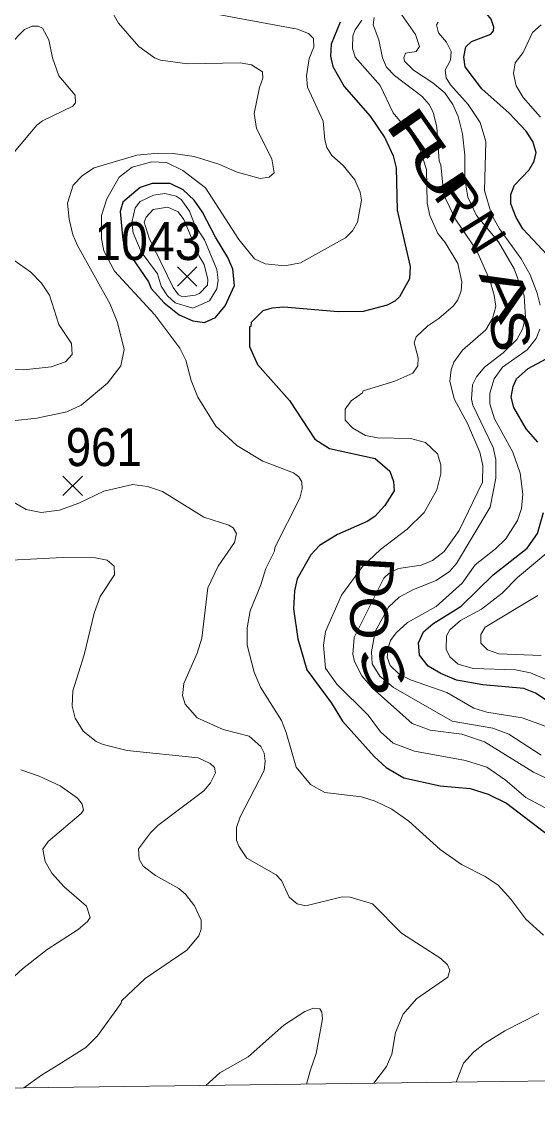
# Model space of a CAD drawing. Extents: x 265 to 291.4, y 7731.5 to 7759.6.
# Drawn here: x 270.921 to 272.01, y 7731.544 to 7733.87 of the extents above; entities that cross this region are included whole.
import ezdxf
from ezdxf.enums import TextEntityAlignment as Align

# ---------------------------------------------------------------- set-up
doc = ezdxf.new("R2010")
doc.units = 0
doc.header["$LTSCALE"] = 0.032
for name, color, linetype, lineweight in [('1', 7, 'Continuous', 25), ('2', 7, 'Continuous', 13), ('21', 7, 'Continuous', 25), ('61', 7, 'Continuous', 13), ('63', 7, 'Continuous', 25)]:
    doc.layers.add(name, color=color, linetype=linetype, lineweight=lineweight)

msp = doc.modelspace()

# ---------------------------------------------------------------- linework, layer by layer
at = {"layer": '1'}
for points in [[(271.9111, 7733.8446), (271.9166, 7733.8518), (271.9174, 7733.8589), (271.9118, 7733.8764), (271.8657, 7733.9329), (271.8538, 7733.9552), (271.8466, 7733.9775)], [(271.5929, 7733.8701), (271.5738, 7733.8231), (271.5722, 7733.7977), (271.5777, 7733.7762), (271.6016, 7733.734), (271.6565, 7733.6712), (271.6875, 7733.6259), (271.705, 7733.5877), (271.7114, 7733.5622), (271.713, 7733.4731), (271.7408, 7733.3538), (271.7392, 7733.3283), (271.7185, 7733.2902), (271.7082, 7733.2806), (271.6923, 7733.2726), (271.6414, 7733.2591), (271.5889, 7733.2583), (271.4743, 7733.2679), (271.4489, 7733.2663), (271.4298, 7733.2607), (271.4051, 7733.2361), (271.4043, 7733.2273), (271.4019, 7733.2265), (271.4019, 7733.1852), (271.4186, 7733.147), (271.4863, 7733.0714), (271.5396, 7732.9895), (271.5706, 7732.9696), (271.6669, 7732.9489), (271.6979, 7732.9218), (271.7058, 7732.9004), (271.7066, 7732.8805), (271.6875, 7732.8495), (271.666, 7732.8264), (271.6501, 7732.816), (271.5873, 7732.7882), (271.5491, 7732.7651), (271.5308, 7732.7452), (271.5022, 7732.6951), (271.4966, 7732.6697), (271.4942, 7732.6315), (271.5038, 7732.5679), (271.5228, 7732.5026), (271.5746, 7732.4326), (271.5976, 7732.3945)], [(272.0717, 7733.3347), (271.9787, 7733.4334), (271.9643, 7733.4572), (271.9532, 7733.4866), (271.9532, 7733.5057), (271.9612, 7733.5256), (271.9922, 7733.5582), (272.0025, 7733.5765), (272.0065, 7733.5948), (271.9993, 7733.6179), (271.9858, 7733.6394), (271.95, 7733.6776), (271.892, 7733.7293), (271.857, 7733.7754), (271.8538, 7733.7961), (271.8585, 7733.8176), (271.8705, 7733.8287), (271.9111, 7733.8446)], [(272.0105, 7732.9831), (271.9858, 7733.0117), (271.9596, 7733.0563), (271.954, 7733.0786), (271.958, 7733.1008), (271.9651, 7733.1167), (271.9898, 7733.139), (272.028, 7733.1589)], [(272.0487, 7732.4247), (272.0049, 7732.4533), (271.9803, 7732.4636), (271.8944, 7732.4708), (271.8387, 7732.4811), (271.8053, 7732.4947), (271.779, 7732.5106), (271.7607, 7732.5337), (271.7583, 7732.5599), (271.7686, 7732.583), (271.7885, 7732.5997), (271.8482, 7732.637), (271.9158, 7732.7031), (271.9874, 7732.7596), (272.0097, 7732.7906), (272.0224, 7732.8351)], [(271.5976, 7732.3945), (271.6644, 7732.3197), (271.6899, 7732.2966), (271.7273, 7732.2751), (271.8037, 7732.2576), (271.8673, 7732.252), (271.9055, 7732.2401)], [(271.9055, 7732.2401), (271.9437, 7732.221), (272.0479, 7732.1415), (272.106, 7732.0866), (272.1601, 7732.0468), (272.1855, 7732.0357), (272.211, 7732.0293), (272.2746, 7732.0245), (272.2953, 7732.0197), (272.304, 7732.0015), (272.3016, 7731.9888), (272.2451, 7731.8487), (272.2268, 7731.8233), (272.1616, 7731.762), (272.1417, 7731.7374), (272.1378, 7731.7247), (272.1339, 7731.7104), (272.1322, 7731.6905), (272.1339, 7731.679), (272.138, 7731.6663), (272.1444, 7731.6493), (272.1533, 7731.6367)]]:
    msp.add_lwpolyline(points, dxfattribs=at)
msp.add_lwpolyline([(271.3665, 7733.3484), (271.3559, 7733.3729), (271.3295, 7733.4159), (271.3025, 7733.4684), (271.285, 7733.4938), (271.2619, 7733.5161), (271.2341, 7733.5296), (271.1959, 7733.5296), (271.1705, 7733.5208), (271.1339, 7733.4898), (271.1283, 7733.4699), (271.1339, 7733.4103), (271.1442, 7733.3864), (271.1887, 7733.322), (271.1943, 7733.3077), (271.2214, 7733.2774), (271.2532, 7733.252), (271.2818, 7733.2392), (271.3065, 7733.236), (271.3296, 7733.2464), (271.3502, 7733.2711), (271.3701, 7733.314)], close=True, dxfattribs=at)
at = {"layer": '2'}
for points in [[(270.9096, 7734.0976), (270.9541, 7734.1175), (270.9668, 7734.1167), (270.9796, 7734.1111), (271.0082, 7734.0761), (271.0416, 7734.026), (271.0917, 7733.9266), (271.1251, 7733.8677), (271.1681, 7733.8184), (271.2007, 7733.7945), (271.2134, 7733.7897), (271.2707, 7733.7818), (271.3821, 7733.7842), (271.4059, 7733.7794), (271.429, 7733.7651), (271.4298, 7733.7515), (271.4226, 7733.7317), (271.4115, 7733.6768), (271.4163, 7733.645), (271.4489, 7733.5813)], [(272.0169, 7732.3228), (271.9492, 7732.3666), (271.915, 7732.3793), (271.8291, 7732.3944), (271.7058, 7732.4652), (271.6764, 7732.4891), (271.6605, 7732.5154), (271.6589, 7732.5408), (271.6668, 7732.5838), (271.6947, 7732.6347), (271.7178, 7732.6562), (271.748, 7732.6721), (271.7957, 7732.6912), (271.8236, 7732.7102), (271.8387, 7732.727), (271.9095, 7732.8463), (271.9214, 7732.9075), (271.9214, 7732.9465), (271.9158, 7732.972), (271.8729, 7733.0611), (271.8705, 7733.0738), (271.8721, 7733.104), (271.8808, 7733.1215), (271.8975, 7733.1414), (271.9373, 7733.1716), (271.9659, 7733.2003), (271.9779, 7733.2218), (271.9842, 7733.2472), (271.9811, 7733.2918), (271.9604, 7733.349), (271.927, 7733.4063), (271.8808, 7733.462), (271.8625, 7733.5002), (271.8562, 7733.5384), (271.8562, 7733.5893), (271.8514, 7733.6338), (271.8419, 7733.6704), (271.8307, 7733.6959), (271.814, 7733.7205), (271.7886, 7733.742), (271.748, 7733.7682), (271.7289, 7733.7873), (271.7273, 7733.7945), (271.7305, 7733.804), (271.7535, 7733.808), (271.7607, 7733.8184), (271.752, 7733.8438), (271.7026, 7733.9138)], [(272.0224, 7731.9426), (271.985, 7731.9768), (271.9532, 7732.019), (271.9262, 7732.0484), (271.8991, 7732.0667), (271.849, 7732.0922), (271.8037, 7732.1232), (271.7376, 7732.1836), (271.7019, 7732.2083), (271.6669, 7732.2258), (271.6382, 7732.2346), (271.5603, 7732.2441), (271.53, 7732.2608), (271.4998, 7732.2974), (271.4791, 7732.3706), (271.4688, 7732.396), (271.425, 7732.466), (271.4115, 7732.4979), (271.3964, 7732.5551), (271.3964, 7732.5917), (271.4027, 7732.6275), (271.4258, 7732.6824), (271.4362, 7732.7166), (271.4545, 7732.7532), (271.4552, 7732.7612), (271.5077, 7732.8654), (271.5125, 7732.8845), (271.5117, 7732.8996), (271.5054, 7732.9099), (271.4942, 7732.9187), (271.4298, 7732.9433), (271.3749, 7732.9759), (271.3304, 7733.0173), (271.2922, 7733.0786), (271.2786, 7733.1136), (271.2675, 7733.1565), (271.2548, 7733.182), (271.2015, 7733.252), (271.1168, 7733.3439), (271.0939, 7733.3871), (271.0893, 7733.4127), (271.0893, 7733.462), (271.1005, 7733.497), (271.1267, 7733.5423), (271.1538, 7733.5638), (271.1951, 7733.5749), (271.2262, 7733.5733), (271.2612, 7733.5566), (271.3089, 7733.52), (271.3789, 7733.4111), (271.4123, 7733.3705), (271.4346, 7733.3594), (271.4759, 7733.3554), (271.5093, 7733.3618), (271.604, 7733.4143), (271.6191, 7733.4294), (271.6295, 7733.4477), (271.6382, 7733.4938), (271.635, 7733.5113), (271.6239, 7733.5368), (271.5992, 7733.567), (271.5754, 7733.5885), (271.565, 7733.6052), (271.5603, 7733.6211), (271.5571, 7733.6609), (271.5237, 7733.7325), (271.5221, 7733.7563), (271.5276, 7733.7929), (271.5372, 7733.8168), (271.5364, 7733.8351), (271.526, 7733.8462), (271.503, 7733.855), (271.3089, 7733.8907)], [(271.639, 7733.8741), (271.6247, 7733.8534), (271.6199, 7733.8406), (271.6191, 7733.8152), (271.6247, 7733.7961), (271.6772, 7733.7364), (271.705, 7733.6784), (271.7416, 7733.6338), (271.7615, 7733.6004), (271.775, 7733.559), (271.7766, 7733.4874), (271.7822, 7733.462), (271.7989, 7733.4238), (271.8148, 7733.4047), (271.8411, 7733.3602), (271.8498, 7733.322), (271.8482, 7733.3029), (271.8411, 7733.2838), (271.8323, 7733.2711), (271.8013, 7733.244), (271.7782, 7733.2289), (271.7535, 7733.2058), (271.7488, 7733.1931), (271.7575, 7733.1613), (271.7567, 7733.1446), (271.7464, 7733.1287), (271.7082, 7733.112), (271.6414, 7733.0913)], [(271.6645, 7733.8796), (271.6629, 7733.8645), (271.6748, 7733.8327), (271.682, 7733.7945), (271.6907, 7733.7746), (271.7074, 7733.7571), (271.7663, 7733.7126), (271.7806, 7733.6959), (271.7893, 7733.68), (271.7973, 7733.6481), (271.8021, 7733.5765), (271.8053, 7733.5686), (271.8116, 7733.5049), (271.8371, 7733.4524), (271.8808, 7733.3888), (271.9087, 7733.3252), (271.9182, 7733.2933), (271.9214, 7733.2695), (271.9142, 7733.244), (271.9007, 7733.2202), (271.8514, 7733.1772), (271.8331, 7733.1518), (271.8275, 7733.1358), (271.8244, 7733.112), (271.8339, 7733.0746), (271.8617, 7733.0229), (271.888, 7732.9624), (271.8944, 7732.9338), (271.8936, 7732.8988), (271.8442, 7732.797), (271.8124, 7732.7524), (271.7878, 7732.7333), (271.7639, 7732.7238), (271.7162, 7732.7166), (271.6963, 7732.7071), (271.6851, 7732.6959), (271.6223, 7732.571), (271.6199, 7732.536), (271.6231, 7732.5201), (271.639, 7732.4899), (271.6605, 7732.4644), (271.7448, 7732.3897), (271.783, 7732.3753), (271.8498, 7732.3666), (271.8975, 7732.3507), (272.001, 7732.287), (272.0821, 7732.2489)], [(272.0153, 7733.2727), (272.0089, 7733.2981), (271.9938, 7733.3363), (271.9747, 7733.3705), (271.9293, 7733.4334), (271.9126, 7733.4636), (271.8975, 7733.5145), (271.9007, 7733.6179), (271.8888, 7733.6577), (271.8633, 7733.6959), (271.8259, 7733.7372), (271.8164, 7733.7523), (271.8148, 7733.7682), (271.8259, 7733.7897), (271.8275, 7733.808), (271.8172, 7733.8279), (271.8005, 7733.847), (271.7965, 7733.8645), (271.7997, 7733.8701)], [(270.8562, 7733.5384), (270.9525, 7733.6521), (270.9644, 7733.6617), (271.0289, 7733.6927), (271.0344, 7733.6998), (271.0336, 7733.7157), (270.9994, 7733.7563), (270.9859, 7733.7945), (270.978, 7733.8327), (270.9644, 7733.8573), (270.9557, 7733.8613), (270.943, 7733.8613), (270.9263, 7733.8542), (270.8626, 7733.7897)], [(272.0169, 7733.8645), (271.9986, 7733.8478), (271.9795, 7733.8056), (271.962, 7733.7842), (271.9588, 7733.7611), (271.9644, 7733.7356), (271.9795, 7733.711), (272.0161, 7733.6696)], [(271.285, 7733.5861), (271.2405, 7733.5924), (271.2087, 7733.5932), (271.1641, 7733.5893), (271.0734, 7733.5622), (271.0488, 7733.5463), (271.0297, 7733.5256), (271.0177, 7733.4874), (271.0209, 7733.454), (271.0289, 7733.4206), (271.0384, 7733.3984), (271.1076, 7733.2743), (271.1227, 7733.2361), (271.1371, 7733.1788), (271.1299, 7733.1446), (271.1021, 7733.108), (271.0464, 7733.0611), (271.0161, 7733.0475), (270.9525, 7733.034), (270.9016, 7733.0284)], [(271.4489, 7733.5813), (271.4537, 7733.5519), (271.4433, 7733.5423), (271.4242, 7733.5399), (271.3757, 7733.5535), (271.3367, 7733.5702), (271.285, 7733.5861)], [(270.8682, 7733.139), (270.9255, 7733.1358), (270.9827, 7733.1422), (271.013, 7733.1525), (271.0273, 7733.1685), (271.0257, 7733.1915), (270.9994, 7733.2313), (270.9795, 7733.2933), (270.9628, 7733.3188), (270.9398, 7733.3419), (270.8435, 7733.4095)], [(272.028, 7732.3833), (271.9771, 7732.4016), (271.9023, 7732.4135), (271.8753, 7732.4215), (271.818, 7732.4549), (271.7416, 7732.4819), (271.7178, 7732.4939), (271.6987, 7732.5122), (271.6923, 7732.5297), (271.6947, 7732.552), (271.6995, 7732.5647), (271.7114, 7732.5806), (271.7353, 7732.6029), (271.7957, 7732.6363), (271.8506, 7732.6856), (271.8776, 7732.7246), (271.9206, 7732.758), (271.9429, 7732.7795), (271.9675, 7732.8176), (271.9755, 7732.8431), (271.9787, 7732.8733), (271.9731, 7732.9179), (271.9572, 7732.9624), (271.919, 7733.0324), (271.9087, 7733.0642), (271.9087, 7733.0865), (271.9182, 7733.1168), (271.9357, 7733.1414), (271.9874, 7733.178), (272.0065, 7733.2019), (272.0145, 7733.2218)], [(271.6414, 7733.0913), (271.6398, 7733.0873), (271.6159, 7733.0706), (271.6032, 7733.0531), (271.6032, 7733.03), (271.6199, 7733.0125), (271.6462, 7732.9974)], [(271.6462, 7732.9974), (271.6716, 7732.9926), (271.7416, 7732.9911), (271.7734, 7732.9823), (271.7981, 7732.9584), (271.8053, 7732.9354), (271.8053, 7732.9163), (271.7973, 7732.8829), (271.7702, 7732.8351), (271.7345, 7732.7993), (271.678, 7732.7564), (271.6398, 7732.7206), (271.596, 7732.6601), (271.5618, 7732.5838), (271.5579, 7732.5551), (271.5618, 7732.5066), (271.5857, 7732.4724), (271.6517, 7732.4072), (271.678, 7732.3722), (271.705, 7732.3483), (271.7496, 7732.3308), (271.8578, 7732.3117), (271.9023, 7732.2974), (271.9413, 7732.2703), (271.985, 7732.233), (272.0678, 7732.1892)], [(270.9032, 7732.8566), (270.9302, 7732.8415), (270.9621, 7732.8351), (271.0002, 7732.8399), (271.0416, 7732.8542), (271.0941, 7732.8797), (271.1546, 7732.894), (271.1864, 7732.89), (271.2182, 7732.8789), (271.3049, 7732.8248), (271.3582, 7732.8081), (271.3669, 7732.8025), (271.3741, 7732.7906), (271.3701, 7732.7715), (271.3351, 7732.7214), (271.3137, 7732.6761), (271.3009, 7732.5695), (271.2914, 7732.5376), (271.2627, 7732.474), (271.2604, 7732.4485), (271.2659, 7732.4302), (271.2914, 7732.4016), (271.3463, 7732.3769), (271.4012, 7732.3626), (271.4258, 7732.3411), (271.4322, 7732.3268), (271.4346, 7732.3101), (271.4322, 7732.2902), (271.3821, 7732.1924), (271.3741, 7732.1701), (271.3741, 7732.1431), (271.3789, 7732.1303), (271.3956, 7732.1049), (271.4576, 7732.0699), (271.4688, 7732.058), (271.4855, 7732.0229), (271.5022, 7732.0086), (271.5205, 7732.0046), (271.5969, 7732.0237), (271.6144, 7732.0229), (271.6613, 7732.0086), (271.7225, 7731.9466), (271.8053, 7731.8933), (271.8196, 7731.8798), (271.8244, 7731.8686), (271.8204, 7731.8543), (271.7543, 7731.8082), (271.7257, 7731.7756), (271.7098, 7731.7374), (271.7018, 7731.6912), (271.6907, 7731.6658), (271.6641, 7731.6301)], [(272.036, 7732.7556), (271.9675, 7732.6975), (271.9349, 7732.6649), (271.8912, 7732.6307), (271.8466, 7732.6068), (271.8244, 7732.5869), (271.8172, 7732.5742), (271.8164, 7732.5464), (271.8244, 7732.5305), (271.8419, 7732.5146), (271.8737, 7732.5058), (271.9628, 7732.5026), (271.9946, 7732.4963), (272.0328, 7732.4804)], [(270.925, 7731.6202), (270.9624, 7731.6473), (270.9994, 7731.6694), (271.0559, 7731.7056), (271.0806, 7731.7302), (271.1307, 7731.7994), (271.1315, 7731.8042), (271.1816, 7731.8511), (271.2691, 7731.9108), (271.2946, 7731.941), (271.2993, 7731.9553), (271.2993, 7731.9744), (271.2858, 7732.0047), (271.2667, 7732.0293), (271.2524, 7732.0412), (271.2031, 7732.0683), (271.1768, 7732.0882), (271.1689, 7732.1033), (271.1673, 7732.1248), (271.1927, 7732.159), (271.2079, 7732.1741), (271.3049, 7732.2473), (271.3192, 7732.264), (271.3296, 7732.2855), (271.328, 7732.2966), (271.3184, 7732.3053), (271.293, 7732.3173), (271.1434, 7732.3324), (271.0925, 7732.3451), (271.0782, 7732.3515), (271.0503, 7732.373), (271.0336, 7732.4008), (271.0273, 7732.4263), (271.0289, 7732.4581), (271.0527, 7732.5345), (271.0734, 7732.622), (271.0862, 7732.6578), (271.1164, 7732.7031), (271.1156, 7732.7214), (271.1013, 7732.7341), (271.0766, 7732.7389), (271.0066, 7732.7397), (270.8984, 7732.7341)], [(272.0169, 7732.5329), (271.9278, 7732.5368), (271.9039, 7732.5448), (271.8896, 7732.5591), (271.8896, 7732.5774), (271.8991, 7732.5925), (272.0105, 7732.6593)], [(270.9191, 7732.2918), (270.9573, 7732.2783), (271.0018, 7732.2576), (271.0384, 7732.2322), (271.0487, 7732.2194), (271.0511, 7732.2067), (271.0464, 7732.1996), (270.9764, 7732.1407), (270.9652, 7732.124), (270.97, 7732.0985), (270.9843, 7732.0739), (271.0106, 7732.0444), (271.0575, 7732.0039), (271.0655, 7731.98), (271.0599, 7731.9713), (271.04, 7731.9545), (270.9748, 7731.9124), (270.9223, 7731.8718), (270.8777, 7731.8304)], [(271.5221, 7731.6282), (271.5303, 7731.6585), (271.542, 7731.6928), (271.5555, 7731.766), (271.5539, 7731.7803), (271.5499, 7731.7875), (271.5364, 7731.7883), (271.5181, 7731.7819), (271.4743, 7731.7525), (271.3988, 7731.6857), (271.3391, 7731.6523), (271.3095, 7731.6254)], [(271.8379, 7731.6325), (271.853, 7731.6722), (271.8745, 7731.696), (271.8975, 7731.7143), (271.9405, 7731.7406), (272.0121, 7731.7771)]]:
    msp.add_lwpolyline(points, dxfattribs=at)
for points in [[(271.3063, 7733.4103), (271.2863, 7733.4415), (271.2747, 7733.4707), (271.2572, 7733.4954), (271.2468, 7733.5026), (271.223, 7733.5081), (271.1991, 7733.5049), (271.1705, 7733.4914), (271.1601, 7733.4779), (271.153, 7733.4469), (271.156, 7733.425), (271.1726, 7733.3851), (271.2071, 7733.3387), (271.215, 7733.3124), (271.2285, 7733.2918), (271.2444, 7733.2774), (271.2818, 7733.2663), (271.3168, 7733.2814), (271.3327, 7733.3069), (271.3351, 7733.3252), (271.3327, 7733.3474)], [(271.1899, 7733.4137), (271.1793, 7733.4476), (271.1832, 7733.458), (271.1983, 7733.4747), (271.2293, 7733.4795), (271.2508, 7733.4691), (271.2627, 7733.4532), (271.2956, 7733.3759), (271.3057, 7733.3586), (271.3137, 7733.3268), (271.3129, 7733.3148), (271.2962, 7733.2973), (271.2866, 7733.2933), (271.2604, 7733.2902), (271.2515, 7733.2942), (271.2402, 7733.3095)]]:
    msp.add_lwpolyline(points, close=True, dxfattribs=at)
at = {"layer": '21'}
for p, q in [((271.2494, 7733.3535), (271.2906, 7733.3123)), ((271.2906, 7733.3535), (271.2494, 7733.3123)), ((271.0078, 7732.9117), (271.049, 7732.8705)), ((271.049, 7732.9117), (271.0078, 7732.8705))]:
    msp.add_line(p, q, dxfattribs=at)
at = {"layer": '63', "lineweight": 13}
msp.add_lwpolyline([(265.3348, 7731.5442), (265.8671, 7731.5515), (266.3994, 7731.5588), (266.9318, 7731.5661), (267.4641, 7731.5734), (267.9964, 7731.5806), (268.5287, 7731.5879), (269.061, 7731.5951), (269.5934, 7731.6023), (270.1257, 7731.6095), (270.658, 7731.6166), (271.1903, 7731.6238), (271.7226, 7731.6309), (272.2549, 7731.638), (272.7872, 7731.6451), (273.3195, 7731.6522), (273.8519, 7731.6593), (274.3842, 7731.6663), (274.9165, 7731.6734), (275.4488, 7731.6804), (275.9811, 7731.6874), (276.5134, 7731.6944), (277.0457, 7731.7013)], dxfattribs=at)

# ---------------------------------------------------------------- texts
at = {"layer": '61'}
for s, rotation, width, p in [('F', 304.965, 1.9, (271.7203, 7733.605)), ('U', 303.2, 1.65, (271.7655, 7733.5381)), ('A', 293.84, 1.65, (271.9084, 7733.2835)), ('S', 279.538, 1.2, (271.9126, 7733.2121)), ('D', 266.583, 1.15, (271.6254, 7732.7002)), ('O', 271.579, 1.1, (271.6142, 7732.6109)), ('S', 293.305, 1.5, (271.6465, 7732.4905))]:
    msp.add_text(s, height=0.08, rotation=rotation, dxfattribs=dict(at, width=width)).set_placement(p, align=Align.CENTER)
for s, rotation, p in [('R', 305.582, (271.8107, 7733.4714)), ('N', 301.851, (271.8598, 7733.4053))]:
    msp.add_text(s, height=0.08, rotation=rotation, dxfattribs=at).set_placement(p, align=Align.CENTER)
for s, width, p in [('1043', 0.95, (271.1871, 7733.3677)), ('961', 0.9, (271.094, 7732.9328))]:
    msp.add_text(s, height=0.08, dxfattribs=dict(at, width=width)).set_placement(p, align=Align.CENTER)

doc.saveas('drawing.dxf')
